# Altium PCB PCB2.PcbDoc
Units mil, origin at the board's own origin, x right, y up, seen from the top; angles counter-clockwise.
Board outline 3935 x 3935 mil, 2 copper layers (Top Layer, Bottom Layer); 63 components, 65 nets, 255 pads, 4 vias.
Unrouted connection lines stored in the file: 1.
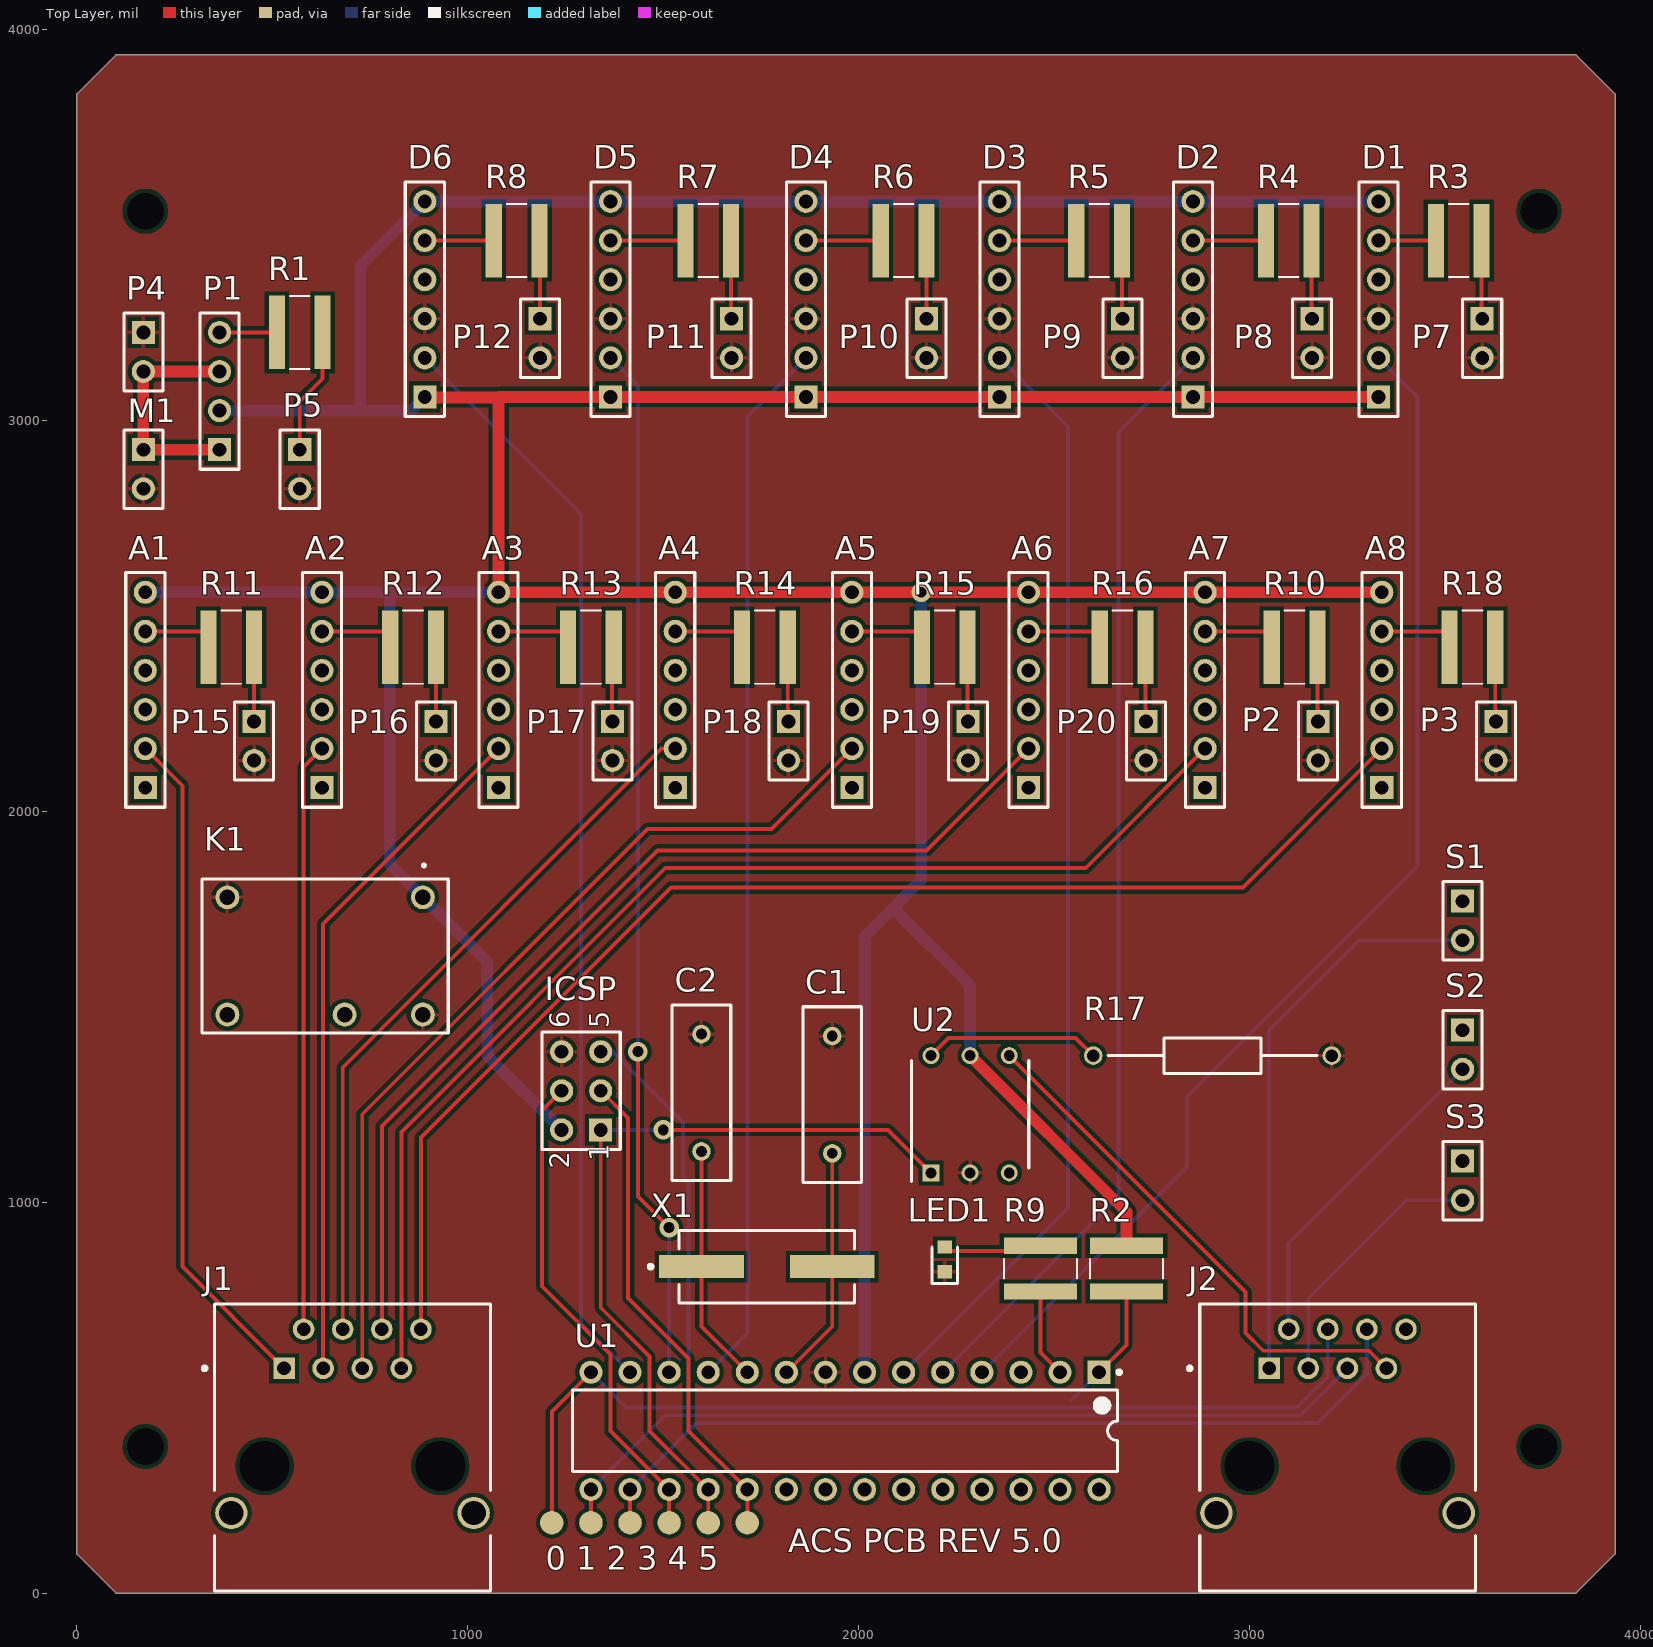
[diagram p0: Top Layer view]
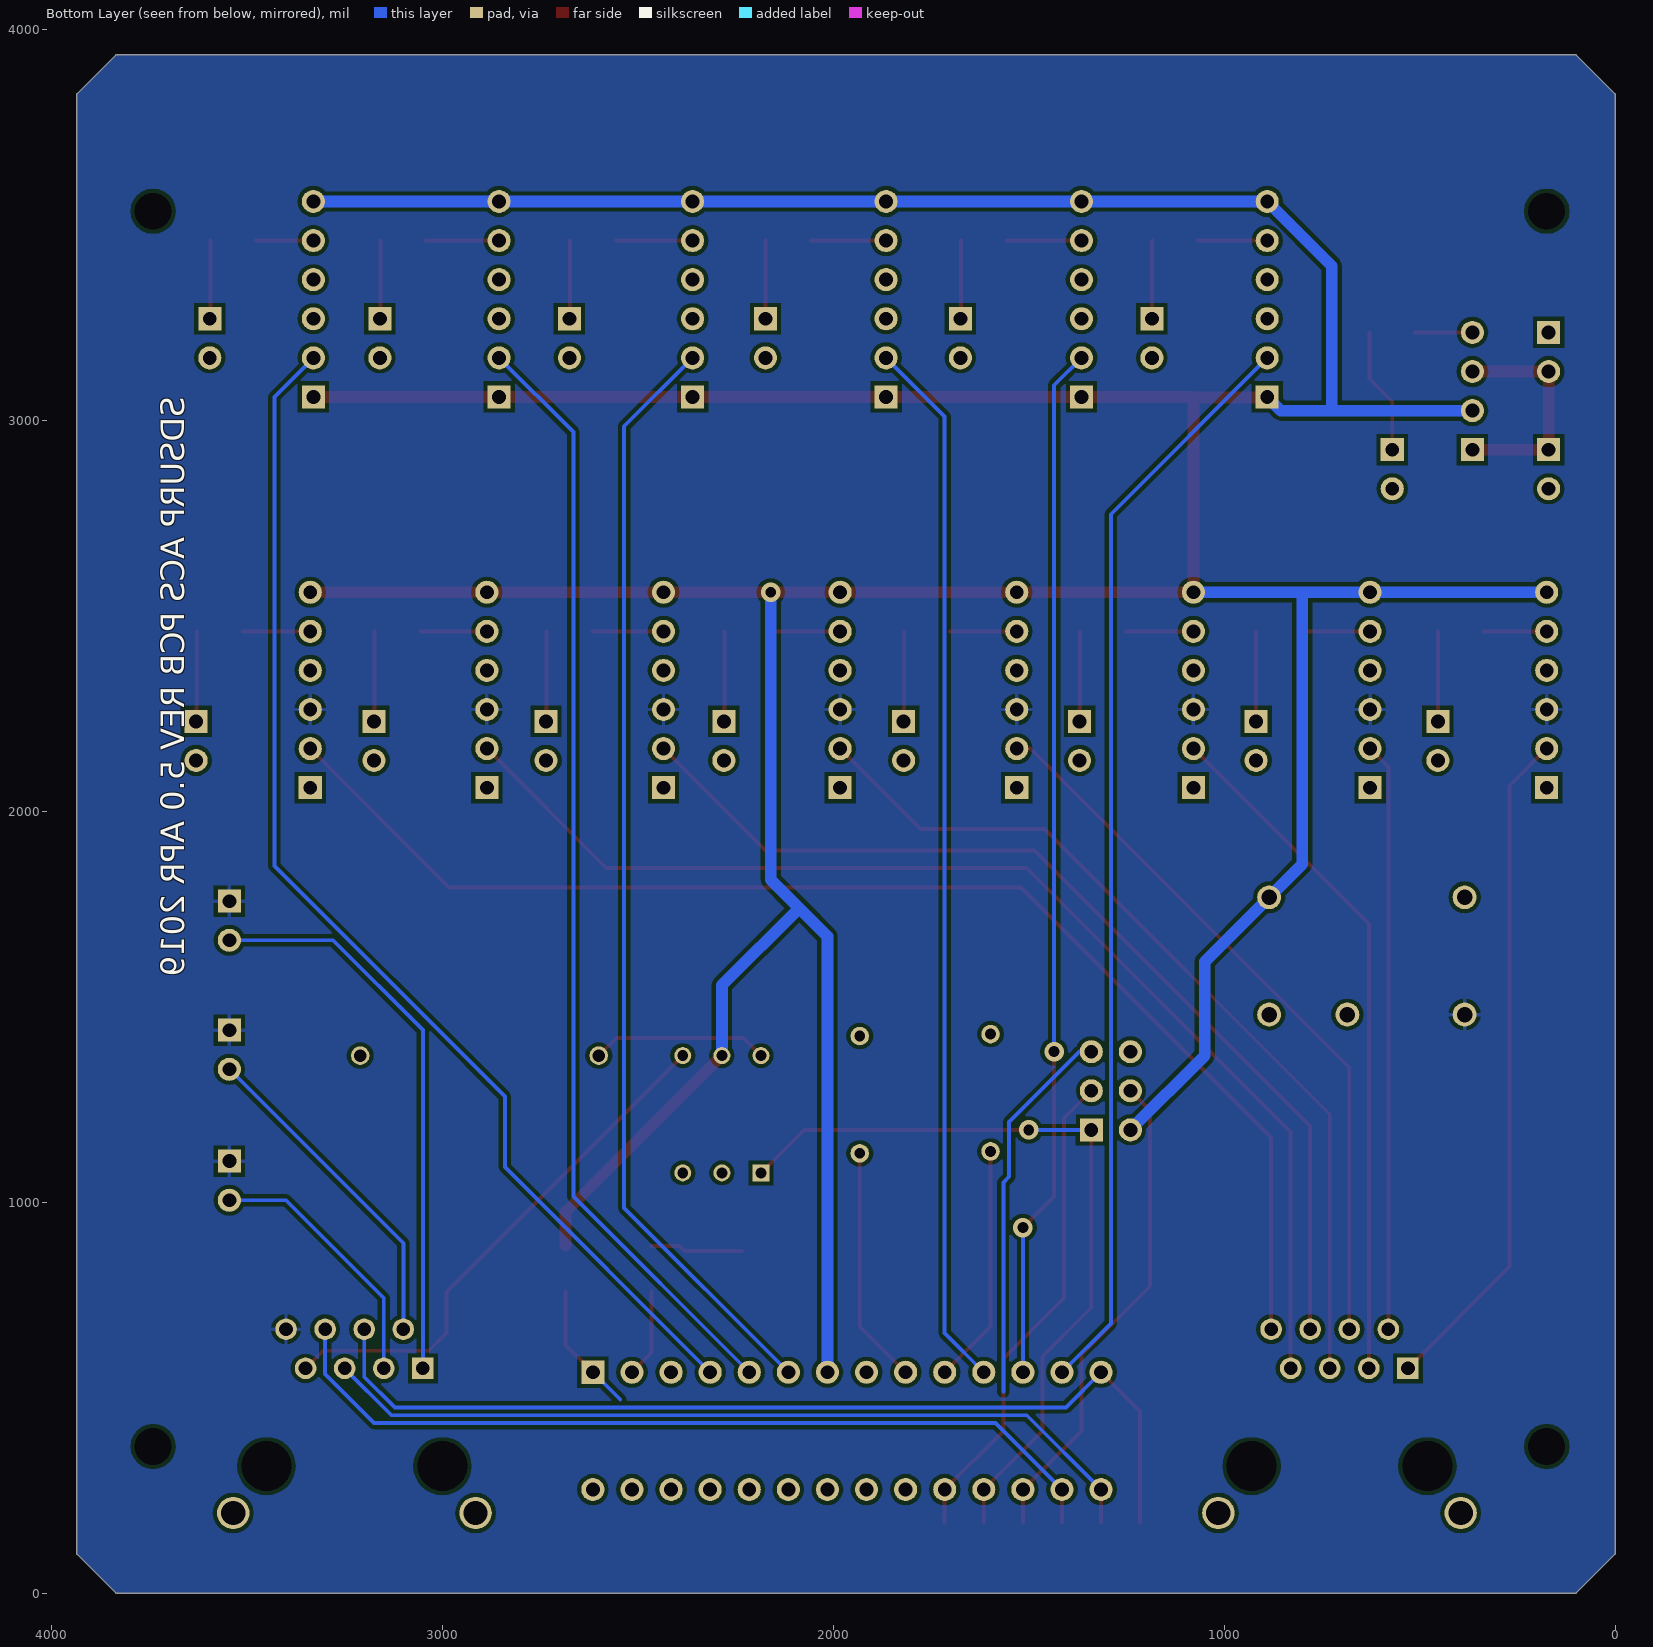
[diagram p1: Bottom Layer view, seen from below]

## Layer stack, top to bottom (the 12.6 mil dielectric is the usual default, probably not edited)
Top Solder: solder mask 0.4, Solder Resist, Dk 3.5
Top Layer: signal copper 1.4
Dielectric 1: dielectric 12.6, FR-4, Dk 4.8
Bottom Layer: signal copper 1.4
Bottom Solder: solder mask 0.4, Solder Resist, Dk 3.5

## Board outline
0,100 0,3835 100,3935 3835,3935 3935,3835 3935,100 3835,0 100,0

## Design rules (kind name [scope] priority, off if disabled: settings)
BoardOutlineClearance [All] p1: gap=7.87 ignorepadtopadclearanceinfootprint=FALSE except(15.75: Arc-SplitBarrior Arc-SplitContinuation Track-SplitBarrior Track-SplitContinuation SMDPad-SplitBarrior SMDPad-SplitContinuation THPad-SplitBarrior THPad-SplitContinuation Via-SplitBarrior Via-SplitContinuation Fill-SplitBarrior Fill-SplitContinuation Poly-SplitBarrior Poly-SplitContinuation Region-SplitBarrior Region-SplitContinuation Text-SplitBarrior Text-SplitContinuation)
Clearance [All] p1: gap=10 ignorepadtopadclearanceinfootprint=FALSE except(0: Arc-Hole Track-Hole SMDPad-Hole THPad-Hole Via-Hole Fill-Hole Poly-Hole Region-Hole Text-Hole)
PolygonConnect [All] p1: connectstyle=Relief reliefconductorwidth=10 reliefentries=4 polygonreliefangle="90 Angle" airgapwidth=10
RoutingVias [All] p1: holewidth=28 width=50 viastyle="Through Hole" minholewidth=28 minwidth=50 maxholewidth=28 maxwidth=50
SolderMaskExpansion [All] p1: expansion=4
Width power [(InNet('NetM1_1') OR InNet('VCC'))] p1: maxlimit=30 minlimit=30 preferedwidth=30 minimp=50.000000 maximp=50.000000 favimp=50.000000
Width [All] p2: maxlimit=10 minlimit=10 preferedwidth=10
30 further rules are at their usual default settings.

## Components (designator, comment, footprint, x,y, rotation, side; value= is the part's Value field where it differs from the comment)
A1 "ANALOG1" HDR1X6 175,2060.39 r90 top
A2 "ANALOG2" HDR1X6 626.86,2060.39 r90 top
A3 "ANALOG3" HDR1X6 1078.73,2060.39 r90 top
A4 "ANALOG4" HDR1X6 1530.59,2060.39 r90 top
A5 "ANALOG5" HDR1X6 1982.45,2060.39 r90 top
A6 "ANALOG6" HDR1X6 2434.32,2060.39 r90 top
A7 "ANALOG7" HDR1X6 2886.18,2060.39 r90 top
A8 "ANALOG8" HDR1X6 3338.04,2060.39 r90 top
C1 "Cap" RAD-0.3 1932.32,1275 r90 top value=22pF
C2 "Cap" RAD-0.3 1597.68,1280 r90 top value=22pF
D1 "DIGITAL1" HDR1X6 3330,3060 r90 top
D2 "DIGITAL2" HDR1X6 2855,3060 r90 top
D3 "DIGITAL3" HDR1X6 2360,3060 r90 top
D4 "DIGITAL4" HDR1X6 1865,3060 r90 top
D5 "DIGITAL5" HDR1X6 1365,3060 r90 top
D6 "IGNITER" HDR1X6 890,3060 r90 top
ICSP "ICSP" HDR2X3 1340,1185 r90 top
J1 "ETH0" TECO-5555153-1_V 705,325 r0 top
J2 "ETH1" TECO-5555153-1_V 3225,325 r0 top
K1 "G6E-134P-ST-US-DC6" G6E-134P-US 949.96,1630 r180 top
LED1 "SML-D12U1WT86" LEDC1608X65N 2220,853.5 r90 top
M1 "MLTM" HDR1X2 170,2925 r270 top
P1 "ABT" HDR1X4 365,2925 r90 top
P2 "LOX VNT LED" HDR1X2 3175,2230 r270 top
P3 "LOX VNT LED" HDR1X2 3630,2230 r270 top
P4 "PWR" HDR1X2 170,3225 r270 top
P5 "ABT LED" HDR1X2 570,2925 r270 top
P7 "D1_LED" HDR1X2 3595,3260 r270 top
P8 "D2_LED" HDR1X2 3160,3260 r270 top
P9 "D3_LED" HDR1X2 2675,3260 r270 top
P10 "D4_LED" HDR1X2 2173.46,3260 r270 top
P11 "D5_LED" HDR1X2 1675,3260 r270 top
P12 "D6_LED" HDR1X2 1185,3260 r270 top
P15 "LOX VNT LED" HDR1X2 453.42,2230 r270 top
P16 "LOX VNT LED" HDR1X2 918.46,2230 r270 top
P17 "LOX VNT LED" HDR1X2 1370,2230 r270 top
P18 "LOX VNT LED" HDR1X2 1820,2230 r270 top
P19 "LOX VNT LED" HDR1X2 2280,2230 r270 top
P20 "LOX VNT LED" HDR1X2 2735,2230 r270 top
R1 "Res3" *RESC3146X60N 570,3225 r180 top value=220
R2 "Res3" *RESC3146X60N 2685,830 r270 top value=10K
R3 "Res3" *RESC3146X60N 3535.04,3460 r180 top value=220
R4 "Res3" *RESC3146X60N 3100,3460 r180 top value=220
R5 "Res3" *RESC3146X60N 2615,3460 r180 top value=220
R6 "Res3" *RESC3146X60N 2115,3460 r180 top value=220
R7 "Res3" *RESC3146X60N 1615,3460 r180 top value=220
R8 "Res3" *RESC3146X60N 1125,3460 r180 top value=220
R9 "Res3" *RESC3146X60N 2465,830 r270 top value=220
R10 "Res3" *RESC3146X60N 3115,2420 r180 top value=220
R11 "Res3" *RESC3146X60N 394.96,2420 r180 top value=220
R12 "Res3" *RESC3146X60N 860,2420 r180 top value=220
R13 "Res3" *RESC3146X60N 1315,2420 r180 top value=220
R14 "Res3" *RESC3146X60N 1760,2420 r180 top value=220
R15 "Res3" *RESC3146X60N 2220,2420 r180 top value=220
R16 "Res3" *RESC3146X60N 2675,2420 r180 top value=220
R17 "1M" RESAD1550W60L630D230 2600,1375 r0 top
R18 "Res3" *RESC3146X60N 3570,2420 r180 top value=220
S1 "IGN SFT" HDR1X2 3545,1770 r270 top
S2 "PRESS SFT" HDR1X2 3545,1440 r270 top
S3 "LNCH SFT" HDR1X2 3545,1105 r270 top
U1 "ATmega328P-PU" 28P3 1965,415 r270 top
U2 "4N35" DIP762W50P254L712H450Q6N 2285,1225 r90 top
X1 "16MHz Clock" CFM-HCM49-2_V 1765,835 r0 top

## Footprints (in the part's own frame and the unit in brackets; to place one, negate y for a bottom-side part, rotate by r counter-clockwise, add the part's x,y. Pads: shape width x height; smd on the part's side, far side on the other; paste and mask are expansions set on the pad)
28P3 [mm] "28-Pin Plastic Dual In-Line Package (PDIP)"
  rect 1.5x1.5 hole 0.9: 1(-3.81,16.51)
  round 1.5 hole 0.9: 2(-3.81,13.97) 3(-3.81,11.43) 4(-3.81,8.89) 5(-3.81,6.35) 6(-3.81,3.81) 7(-3.81,1.27) 8(-3.81,-1.27) 9(-3.81,-3.81) 10(-3.81,-6.35) 11(-3.81,-8.89) 12(-3.81,-11.43) 13(-3.81,-13.97) 14(-3.81,-16.51) 15(3.81,-16.51) 16(3.81,-13.97) 17(3.81,-11.43) 18(3.81,-8.89) 19(3.81,-6.35) 20(3.81,-3.81) 21(3.81,-1.27) 22(3.81,1.27) 23(3.81,3.81) 24(3.81,6.35) 25(3.81,8.89) 26(3.81,11.43) 27(3.81,13.97) 28(3.81,16.51)
  silkscreen extent -3.93,-17.7 2.65,17.94, body extent -3.6,-17.65 3.6,17.65, height 4.58
*RESC3146X60N [mm]
  rect 1.05x4.77 smd: 1(-1.485,0) 2(1.485,0)
  silkscreen extent -0.64,-2.38 0.64,2.38
CFM-HCM49-2_V [mm] "SMD, 2-Leads, Body 11.4x4.7mm, Pitch 8.5mm"
  rect 5.5x1.5 smd: 1(-4.25,0) 2(4.25,0)
  silkscreen extent -7.67,-2.35 5.7,2.35, body extent -5.7,-2.35 5.7,2.35, height 4.3
DIP762W50P254L712H450Q6N [mm]
  rect 1.1x1.1 hole 0.7: 1(-3.81,2.54)
  round 1.1 hole 0.7: 2(-3.81,0) 3(-3.81,-2.54) 4(3.81,-2.54) 5(3.81,0) 6(3.81,2.54)
  silkscreen extent -4.36,-3.81 3.5,3.81, body extent -3.94,-3.56 3.94,3.56, height 4.5
G6E-134P-US [mm]
  round 1.55 hole 1: 1(1.65,-3.81) 6(14.35,-3.81) 7(14.35,3.81) 10(6.73,3.81) 12(1.65,3.81)
  silkscreen extent 0,-5.97 16,5
HDR1X2 [mm] "Connector; Header; 2 Position"
  rect 1.5x1.5 hole 0.9: 1(0,0)
  round 1.5 hole 0.9: 2(2.54,0)
  silkscreen extent -1.27,-1.27 3.81,1.27
HDR1X4 [mm] "Connector; Header; 4 Position"
  rect 1.5x1.5 hole 0.9: 1(0,0)
  round 1.5 hole 0.9: 2(2.54,0) 3(5.08,0) 4(7.62,0)
  silkscreen extent -1.27,-1.27 8.89,1.27
HDR1X6 [mm] "Connector; Header; 6 Position"
  rect 1.5x1.5 hole 0.9: 1(0,0)
  round 1.5 hole 0.9: 2(2.54,0) 3(5.08,0) 4(7.62,0) 5(10.16,0) 6(12.7,0)
  silkscreen extent -1.27,-1.27 13.97,1.27
HDR2X3 [mm] "Connector; Header; 3x2 Position"
  rect 1.5x1.5 hole 0.9: 1(0,0)
  round 1.5 hole 0.9: 2(0,2.54) 3(2.54,0) 4(2.54,2.54) 5(5.08,0) 6(5.08,2.54)
  silkscreen extent -1.27,-1.27 6.35,3.81
LEDC1608X65N [mm]
  rect 0.85x0.95 smd: 1(-0.8,0) 2(0.8,0)
  silkscreen extent -1.58,-0.82 0.8,0.82
RAD-0.3 [mm] "Radial Cap, Thru-Hole; 2 Leads; 0.3 in Pin Spacing"
  round 1.2 hole 0.7: 1(-3.81,0) 2(3.81,0)
  silkscreen extent -5.71,-1.91 5.71,1.91
RESAD1550W60L630D230 [mm]
  round 1.2 hole 0.8: 1(0,0) 2(15.5,0)
  silkscreen extent 0.95,-1.15 14.55,1.15, body extent -0.3,-1.25 15.8,1.25, height 2.49
TECO-5555153-1_V [mm] "RJ45, 8-Leads, Body 18.67x17.91mm, Pitch 1.27mm"
  rect 1.4x1.4 hole 0.89: 1(-4.445,6.35)
  round 1.4 hole 0.89: 2(-3.175,8.89) 3(-1.905,6.35) 4(-0.635,8.89) 5(0.635,6.35) 6(1.905,8.89) 7(3.175,6.35) 8(4.445,8.89)
  round 2.95 hole 3.25 unplated: MH1(-5.715,0) MH2(5.715,0)
  round 2.1 hole 1.57: S1(-7.875,-3.05) S2(7.875,-3.05)
  silkscreen extent -9.73,-8.13 8.96,10.54, body extent -8.89,-8.13 8.89,10.54, height 13.2

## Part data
A1 A2 A3 A4 A5 A6 A7 A8 D1 D2 D3 D4 D5 D6: library part "Header 6", "Header, 6-Pin"
C1 C2: "Capacitor"
ICSP: library part "Header 3X2", "Header, 3-Pin, Dual row"
J1 J2: library part CMP-2000-05640-1, "RJ45 Connector, Pitch 1.27 mm, 8 Position, Height 13.08 mm, Tail Length 3.81 mm, -40 to 85 degC, RoHS, Tray", LED Color=DoesNotContainLED, Manufacturer="TE Connectivity", Operating Temperature=-40°C~85°C, Package Description="RJ45 Connector, Pitch 1.27 mm, 8 Position, Height 13.08 mm, Tail Length 3.81 mm", Package Reference=5555153-1, Ratings=Cat3, Standard Package=136
K1: "Relay or Contactor", Manufacturer_Name="Omron Electronics", Mouser Part Number=653-G6E134PSTUSDC6
LED1: "LED", Manufacturer_Name="ROHM Semiconductor", Mouser Part Number=755-SML-D12U1WT86, RS Part Number=1332870
M1 P2 P3 P4 P5 P7 P8 P9 P10 P11 P12 P15 P16 P17 P18 P19 P20 S1 S2 S3: library part "Header 2", "Header, 2-Pin"
P1: library part "Header 4", "Header, 4-Pin"
R1 R2 R3 R4 R5 R6 R7 R8 R9 R10 R11 R12 R13 R14 R15 R16 R18: "Resistor"
R17: library part YR1B1M0CC, "Resistor", Manufacturer_Name="TE Connectivity", Mouser Part Number=279-YR1B1M0CC, RS Part Number=1649061
U1: library part CMP-0095-00013-2, "8-bit AVR Microcontroller, 32KB Flash, 1KB EEPROM, 2KB SRAM, 28-pin PDIP, Industrial Grade (-40°C to 85°C)"
U2: "Transistor", Manufacturer_Name=Isocom, RS Part Number=1712954
X1: library part CMP-1215-00001-1, "At-Cut Crystal Unit, 3.5 to 30 MHz, -40 to 85 degC, 2-Pin 11.4×4.7×4.3 mm SMD, RoHS, Reel", Manufacturer="Citizen Finetech Miyota", Operating Temperature="-40 to 85 degC", PartNumber=HCM49-8.000MABJ-UT

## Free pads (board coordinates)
  round 60 hole 94.49: 2(175,3535) 2(2240,-7420) 3(3740,3535) 3(5805,-7420) 4(175,375) 4(2240,-10580) 5(3740,375) 5(5805,-10580)
  round 60 smd: 6(1315,180) 7(1415,180) 8(1515,180) 9(1615,180) 10(1715,180) 11(1215,180)

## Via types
v1: diameter 50, hole 28, Top Layer to Bottom Layer, 4 vias

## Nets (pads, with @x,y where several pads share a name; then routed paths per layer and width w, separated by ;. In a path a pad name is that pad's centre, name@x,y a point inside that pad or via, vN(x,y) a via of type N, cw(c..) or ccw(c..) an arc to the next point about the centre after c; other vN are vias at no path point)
A1: A1.2 J1.1 | length 1732.4
  Top Layer w10: A1.2 270,2065.39 270,835 J1.1
A2: A2.2 J1.2 | length 1504.8
  Top Layer w10: J1.2 580,2113.53 A2.2
A3: A3.2 J1.3 | length 1771.3
  Top Layer w10: J1.3 630,1711.67 A3.2
A4: A4.2 J1.4 | length 1858.3
  Top Layer w10: J1.4 680,1345 1495.39,2160.39 A4.2
A5: A5.2 J1.5 | length 2289.9
  Top Layer w10: J1.5 730,1225 1460,1955 1777.06,1955 A5.2
A6: A6.2 J1.6 | length 2574.2
  Top Layer w10: J1.6 780,1195 1485,1900 2173.92,1900 A6.2
A7: A7.2 J1.7 | length 3067.3
  Top Layer w10: J1.7 830,1180 1505,1855 2580.79,1855 A7.2
A8: A8.2 J1.8 | length 3360.3
  Top Layer w10: J1.8 880,1165 1520,1805 2982.65,1805 A8.2
GND: C1.2 C2.2 D1.3 D2.3 D3.3 D4.3 D5.3 D6.3 ICSP.6 K1.6 K1.12 LED1.1 M1.2 P2.2 P3.2 P4.1 P5.2 P7.2 P8.2 P9.2 P10.2 P11.2 P12.2 P15.2 P16.2 P17.2 P18.2 P19.2 P20.2 R17.2 U1.8 U2.2
"IGN SFT": J2.1 S1.2 | length 1455.3
  Bottom Layer w10: J2.1 3050,1440 3280,1670 S1.2
IGN_OUT: J2.7 U2.4 | length 1357.9
  Top Layer w10: U2.4 2990,770 2990,665 3035,620 3305,620 J2.7
"LNCH SFT": J2.3 S3.2 | length 678.6
  Bottom Layer w10: J2.3 3150,755 3400,1005 S3.2
NetA1_5: A1.5 R11.2 | length 161.5
  Top Layer w10: A1.5 R11.2@336.5,2460.39
NetA2_5: A2.5 R12.2 | length 174.8
  Top Layer w10: A2.5 801.14,2460.39 R12.2@801.54,2460
NetA3_5: A3.5 R13.2 | length 173
  Top Layer w10: A3.5 1251.14,2460.39 R13.2@1251.54,2460
NetA4_5: A4.5 R14.2 | length 171.1
  Top Layer w10: A4.5 1701.14,2460.39 R14.2@1701.54,2460
NetA5_5: A5.5 R15.2 | length 179.1
  Top Layer w10: A5.5 R15.2@2161.54,2460.39
NetA6_5: A6.5 R16.2 | length 182.4
  Top Layer w10: A6.5 2616.14,2460.39 R16.2@2616.54,2460
NetA7_5: A7.5 R10.2 | length 170.5
  Top Layer w10: A7.5 2886.57,2460 R10.2@3056.54,2460
NetA8_5: A8.5 R18.2 | length 173.5
  Top Layer w10: A8.5 R18.2@3511.54,2460.39
NetC1_1: C1.1 U1.9 X1.2 | length 608.6
  Top Layer w10: U1.9 1932.32,682.32 X1.2 C1.1
NetC2_1: C2.1 U1.10 X1.1 | length 613.6
  Top Layer w10: C2.1 X1.1 1597.68,682.32 U1.10
NetD1_5: D1.5 R3.2 | length 146.6
  Top Layer w10: D1.5 R3.2
NetD2_5: D2.5 R4.2 | length 186.5
  Top Layer w10: D2.5 R4.2
NetD3_5: D3.5 R5.2 | length 196.5
  Top Layer w10: D3.5 R5.2
NetD4_5: D4.5 R6.2 | length 191.5
  Top Layer w10: D4.5 R6.2
NetD5_5: D5.5 R7.2 | length 191.5
  Top Layer w10: D5.5 R7.2
NetD6_5: D6.5 R8.2 | length 176.5
  Top Layer w10: D6.5 R8.2
NetLED1_2: LED1.2 R9.1 | length 237.1
  Top Layer w10: LED1.2@2233.5,875 2380,875 2393.46,888.46 R9.1
NetM1_1: M1.1 P1.1 P1.3 P4.2 | length 590
  Top Layer w30: P1.1 M1.1 P4.2 P1.3
NetP1_4: P1.4 R1.2 | length 146.5
  Top Layer w10: P1.4 R1.2
NetP2_1: P2.1 R10.1 | length 200.6
  Top Layer w10: R10.1@3173.46,2460 3173.46,2261.54 3175,2260
NetP3_1: P3.1 R18.1 | length 201
  Top Layer w10: R18.1@3628.46,2460.39 3628.46,2261.54 3630,2260
NetP5_1: P5.1 R1.1 | length 324.2
  Top Layer w10: P5.1 570,3048.14 628.46,3106.6 R1.1
NetP7_1: P7.1 R3.1 | length 200.6
  Top Layer w10: R3.1 3593.5,3261.5 P7.1
NetP8_1: P8.1 R4.1 | length 200.6
  Top Layer w10: R4.1 3158.46,3261.54 P8.1
NetP9_1: P9.1 R5.1 | length 200.6
  Top Layer w10: R5.1 2673.46,3261.54 P9.1
NetP10_1: P10.1 R6.1 | length 204.9
  Top Layer w10: P10.1@2170,3260 P10.1@2173.46,3263.46 ; P10.1 P10.1@2173.46,3263.46 ; R6.1 P10.1@2173.46,3263.46
NetP11_1: P11.1 R7.1 | length 200.6
  Top Layer w10: R7.1 1673.46,3261.54 P11.1
NetP12_1: P12.1 R8.1 | length 200.6
  Top Layer w10: R8.1 1185,3458.46 P12.1
NetP15_1: P15.1 R11.1 | length 200
  Top Layer w10: 453.42,2260.39 R11.1@453.42,2460.39
NetP16_1: P16.1 R12.1 | length 199.6
  Top Layer w10: 918.46,2260.39 R12.1@918.46,2460
NetP17_1: P17.1 R13.1 | length 200.2
  Top Layer w10: R13.1@1368.46,2460 1368.46,2261.93 1370,2260.39
NetP18_1: P18.1 R14.1 | length 200.2
  Top Layer w10: R14.1@1818.46,2460 1818.46,2261.93 1820,2260.39
NetP19_1: P19.1 R15.1 | length 200.6
  Top Layer w10: R15.1@2278.46,2460.39 2278.46,2261.93 2280,2260.39
NetP20_1: P20.1 R16.1 | length 200.6
  Top Layer w10: R16.1@2733.46,2460 2733.46,2261.54 2735,2260
NetR17_1: R17.1 U2.6 | length 452.3
  Top Layer w10: U2.6 2230,1420 2555,1420 R17.1
PB0: J2.4 pad.11 U1.14 | length 2502.8
  Top Layer w10: pad.11 1215,465 U1.14
  Bottom Layer w10: U1.14 1405,475 3121.72,475 3200,553.28 J2.4
PB1: J2.5 pad.6 U1.15 | length 2148.4
  Top Layer w10: pad.6 U1.15
  Bottom Layer w10: U1.15 1505,455 3130,455 J2.5
PB2: J2.6 pad.7 U1.16 | length 2217.4
  Top Layer w10: pad.7 U1.16
  Bottom Layer w10: U1.16 1585,435 3175,435 3300,560 J2.6 J2.6@3289.81,675
PB3: ICSP.4 pad.8 U1.17 | length 1260.3
  Top Layer w10: ICSP.4 1190,1235 1190,785 1365,610 1365,415 U1.17 pad.8
PB4: ICSP.1 pad.9 U1.18 U2.1 | length 2009.5
  Top Layer w10: ICSP.1 1340,730 1465,605 1465,415 U1.18 pad.9 ; v1(1500,1185) 2075,1185 U2.1
  Bottom Layer w10: ICSP.1 v1(1500,1185)
PB5: ICSP.3 pad.10 U1.19 | length 1260.3
  Top Layer w10: ICSP.3 1410,1215 1410,755 1565,600 1565,415 U1.19 pad.10
PD0: R9.2 U1.2 | length 227.2
  Top Layer w10: R9.2 2465,615 U1.2
PD1: U1.3
PD2: D1.2 U1.4 | length 3098.3
  Bottom Layer w10: U1.4 2840,1090 2840,1270 3430,1860 3430,3060 D1.2
PD3: D2.2 U1.5 | length 2860.1
  Bottom Layer w10: U1.5 2665,1015 2665,2970 D2.2
PD4: D3.2 U1.6 | length 2841.5
  Bottom Layer w10: U1.6 2535,985 2535,2985 D3.2
PD5: D4.2 U1.11 | length 2698.6
  Bottom Layer w10: U1.11 1715,665 1715,3010 D4.2
PD6: D5.2 U1.12 | length 2657.1
  Top Layer w10: v1(1435,1385) 1435,1015 v1(1515,935)
  Bottom Layer w10: D5.2 1435,3090 v1(1435,1385) ; U1.12 v1(1515,935)
PD7: D6.2 U1.13 | length 2812.5
  Bottom Layer w10: D6.2 1290,2760 1290,690 U1.13
"PRESS SFT": J2.2 S2.2 | length 849.3
  Bottom Layer w10: J2.2 3100,895 S2.2
RST: ICSP.5 R2.2 U1.1 | length 1315.3
  Top Layer w10: U1.1 2685,635 R2.2
  Bottom Layer w10: ICSP.5 1370,1385 1550,1205 1550,1065 1565,1050 1565,515 ; 2545,495 U1.1
SGND: A1.3 A2.3 A3.3 A4.3 A5.3 A6.3 A7.3 A8.3 J2.8 K1.7 S1.1 S2.1 S3.1
VCC: A1.6 A2.6 A3.6 A4.6 A5.6 A6.6 A7.6 A8.6 D1.1 D1.6 D2.1 D2.6 D3.1 D3.6 D4.1 D4.6 D5.1 D5.6 D6.1 D6.6 ICSP.2 K1.1 P1.2 R2.1 U1.7 U2.5 | length 14380.2
  Top Layer w30: D6.1@891.27,3058.73 1078.73,3058.73 A3.6 A4.6 A5.6 v1(2160,2560.39) A6.6 A7.6 A8.6 ; 1080,3060 D5.1 D4.1 D3.1 D2.1 D1.1@3316.02,3060 ; U2.5 2685,975 R2.1
  Bottom Layer w30: A1.6 A2.6 800,2560.39 ; P1.2 725,3025 ; D6.1@891.27,3058.73 D6.1 855,3025 725,3025 ; A3.6 800,2560.39 ; ICSP.2 1050,1375 1050,1615 K1.1 800,1865 800,2560.39 ; U1.7 2015,1680 2087.5,1752.5 ; v1(2160,2560.39) 2160,1825 2087.5,1752.5 ; U2.5 2285,1555 2087.5,1752.5 ; D1.6@3316.02,3560 D2.6 D3.6 D4.6 D5.6 D6.6 725,3395 725,3025
pads on no net: A1.1 A1.4 A2.1 A2.4 A3.1 A3.4 A4.1 A4.4 A5.1 A5.4 A6.1 A6.4 A7.1 A7.4 A8.1 A8.4 D1.4 D2.4 D3.4 D4.4 D5.4 D6.4 J1.MH1 J1.MH2 J1.S1 J1.S2 J2.MH1 J2.MH2 J2.S1 J2.S2 K1.10 U1.20 U1.21 U1.22 U1.23 U1.24 U1.25 U1.26 U1.27 U1.28 U2.3

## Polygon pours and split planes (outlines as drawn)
GND on Top Layer (solid, pour order 0): 0,3835 100,3935 3835,3935 3935,3835 3935,100 3835,0 100,0 0,100
SGND on Bottom Layer (solid, pour order 2): 0,3835 100,3935 3835,3935 3935,3835 3935,100 3835,0 100,0 0,100

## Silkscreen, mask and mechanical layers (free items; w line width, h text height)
Top Overlay:
  text "ACS PCB REV 5.0" at 1820,105 h60
  text "0 1 2 3 4 5" at 1200,60 h60
Bottom Overlay:
  text "SDSURP ACS PCB REV 5.0 APR 2019" at 3660,3060 h60 r270
Mechanical 1:
  the board outline again, w10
